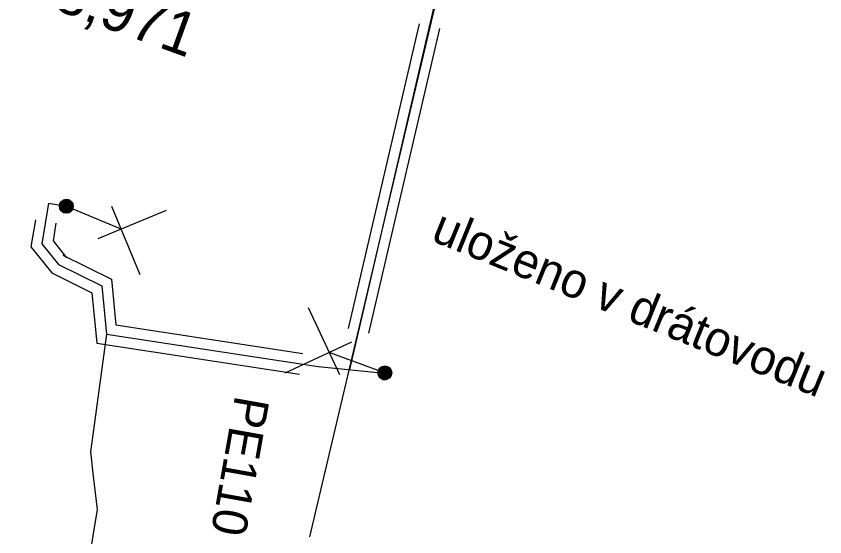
# Model space of a CAD drawing. Extents: x -731967 to -723173, y -945358 to -941505.
# Drawn here: x -725800 to -725776.75, y -942623.44 to -942608.48 of the extents above; entities that cross this region are included whole.
import ezdxf

# ---------------------------------------------------------------- set-up
doc = ezdxf.new("R2010")
doc.units = 0
for name, color, linetype in [('Vrstva 2', 7, 'Continuous'), ('Vrstva 28', 7, 'Continuous'), ('Vrstva 35', 7, 'Continuous')]:
    doc.layers.add(name, color=color, linetype=linetype)

msp = doc.modelspace()

# ---------------------------------------------------------------- linework, layer by layer
at = {"layer": 'Vrstva 2'}
for p, q in [((-725798.375, -942614.017), (-725796.99, -942614.592)), ((-725798.375, -942614.017), (-725796.99, -942614.592)), ((-725797.643, -942614.861), (-725795.683, -942614.051)), ((-725797.643, -942614.861), (-725795.683, -942614.051)), ((-725797.26, -942613.939), (-725796.45, -942615.9)), ((-725797.26, -942613.939), (-725796.45, -942615.9)), ((-725799.451, -942614.327), (-725799.577, -942615.102)), ((-725799.451, -942614.327), (-725799.577, -942615.102)), ((-725798.858, -942614.423), (-725798.942, -942614.937)), ((-725798.858, -942614.423), (-725798.942, -942614.937)), ((-725798.942, -942614.937), (-725798.555, -942615.423)), ((-725798.942, -942614.937), (-725798.555, -942615.423)), ((-725799.577, -942615.102), (-725798.981, -942615.85)), ((-725799.577, -942615.102), (-725798.981, -942615.85)), ((-725790.7, -942618.781), (-725791.595, -942616.857)), ((-725790.7, -942618.781), (-725791.595, -942616.857)), ((-725790.358, -942617.843), (-725792.282, -942618.738)), ((-725790.358, -942617.843), (-725792.282, -942618.738)), ((-725789.59, -942618.655), (-725790.999, -942618.141)), ((-725789.59, -942618.655), (-725790.999, -942618.141))]:
    msp.add_line(p, q, dxfattribs=at)
for points in [[(-725788.418, -942608.698), (-725790.454, -942617.453)], [(-725788.418, -942608.698), (-725790.454, -942617.453)], [(-725787.833, -942608.834), (-725789.87, -942617.589)], [(-725787.833, -942608.834), (-725789.87, -942617.589)], [(-725798.483, -942613.755), (-725798.59, -942613.746), (-725798.696, -942613.803), (-725798.747, -942613.906), (-725798.738, -942614.005), (-725798.671, -942614.093), (-725798.561, -942614.13), (-725798.462, -942614.104), (-725798.395, -942614.032), (-725798.373, -942613.921), (-725798.418, -942613.823), (-725798.496, -942613.772), (-725798.599, -942613.768), (-725798.691, -942613.827), (-725798.729, -942613.915), (-725798.718, -942614.007), (-725798.649, -942614.086), (-725798.551, -942614.111), (-725798.469, -942614.085), (-725798.406, -942614.012), (-725798.395, -942613.911), (-725798.437, -942613.831), (-725798.51, -942613.788), (-725798.606, -942613.791), (-725798.682, -942613.848), (-725798.711, -942613.922), (-725798.694, -942614.01), (-725798.627, -942614.076), (-725798.547, -942614.091), (-725798.472, -942614.063), (-725798.419, -942613.992), (-725798.416, -942613.907), (-725798.454, -942613.842), (-725798.525, -942613.804), (-725798.611, -942613.813), (-725798.67, -942613.863), (-725798.692, -942613.931), (-725798.671, -942614.01), (-725798.611, -942614.062), (-725798.545, -942614.071), (-725798.477, -942614.042), (-725798.434, -942613.976), (-725798.438, -942613.906), (-725798.472, -942613.853), (-725798.539, -942613.822), (-725798.61, -942613.835), (-725798.655, -942613.877), (-725798.673, -942613.941), (-725798.649, -942614.007), (-725798.598, -942614.045), (-725798.541, -942614.052), (-725798.482, -942614.021), (-725798.452, -942613.964), (-725798.456, -942613.909), (-725798.491, -942613.862), (-725798.55, -942613.84), (-725798.605, -942613.854), (-725798.641, -942613.891), (-725798.652, -942613.948), (-725798.63, -942614.001), (-725798.589, -942614.029), (-725798.538, -942614.03), (-725798.49, -942614.001), (-725798.471, -942613.957), (-725798.477, -942613.912), (-725798.508, -942613.873), (-725798.557, -942613.86), (-725798.597, -942613.873), (-725798.626, -942613.906), (-725798.633, -942613.953), (-725798.613, -942613.992), (-725798.58, -942614.01), (-725798.537, -942614.01), (-725798.503, -942613.984), (-725798.49, -942613.952), (-725798.496, -942613.914), (-725798.525, -942613.886), (-725798.559, -942613.88), (-725798.589, -942613.891), (-725798.61, -942613.919), (-725798.612, -942613.955), (-725798.596, -942613.979), (-725798.57, -942613.992), (-725798.539, -942613.99), (-725798.517, -942613.971), (-725798.508, -942613.946), (-725798.517, -942613.919), (-725798.538, -942613.902), (-725798.56, -942613.899), (-725798.58, -942613.908), (-725798.593, -942613.929), (-725798.593, -942613.952), (-725798.582, -942613.968), (-725798.563, -942613.974), (-725798.544, -942613.971), (-725798.533, -942613.958), (-725798.528, -942613.942), (-725798.534, -942613.927), (-725798.547, -942613.919), (-725798.559, -942613.919), (-725798.57, -942613.925)], [(-725798.483, -942613.755), (-725798.59, -942613.746), (-725798.696, -942613.803), (-725798.747, -942613.906), (-725798.738, -942614.005), (-725798.671, -942614.093), (-725798.561, -942614.13), (-725798.462, -942614.104), (-725798.395, -942614.032), (-725798.373, -942613.921), (-725798.418, -942613.823), (-725798.496, -942613.772), (-725798.599, -942613.768), (-725798.691, -942613.827), (-725798.729, -942613.915), (-725798.718, -942614.007), (-725798.649, -942614.086), (-725798.551, -942614.111), (-725798.469, -942614.085), (-725798.406, -942614.012), (-725798.395, -942613.911), (-725798.437, -942613.831), (-725798.51, -942613.788), (-725798.606, -942613.791), (-725798.682, -942613.848), (-725798.711, -942613.922), (-725798.694, -942614.01), (-725798.627, -942614.076), (-725798.547, -942614.091), (-725798.472, -942614.063), (-725798.419, -942613.992), (-725798.416, -942613.907), (-725798.454, -942613.842), (-725798.525, -942613.804), (-725798.611, -942613.813), (-725798.67, -942613.863), (-725798.692, -942613.931), (-725798.671, -942614.01), (-725798.611, -942614.062), (-725798.545, -942614.071), (-725798.477, -942614.042), (-725798.434, -942613.976), (-725798.438, -942613.906), (-725798.472, -942613.853), (-725798.539, -942613.822), (-725798.61, -942613.835), (-725798.655, -942613.877), (-725798.673, -942613.941), (-725798.649, -942614.007), (-725798.598, -942614.045), (-725798.541, -942614.052), (-725798.482, -942614.021), (-725798.452, -942613.964), (-725798.456, -942613.909), (-725798.491, -942613.862), (-725798.55, -942613.84), (-725798.605, -942613.854), (-725798.641, -942613.891), (-725798.652, -942613.948), (-725798.63, -942614.001), (-725798.589, -942614.029), (-725798.538, -942614.03), (-725798.49, -942614.001), (-725798.471, -942613.957), (-725798.477, -942613.912), (-725798.508, -942613.873), (-725798.557, -942613.86), (-725798.597, -942613.873), (-725798.626, -942613.906), (-725798.633, -942613.953), (-725798.613, -942613.992), (-725798.58, -942614.01), (-725798.537, -942614.01), (-725798.503, -942613.984), (-725798.49, -942613.952), (-725798.496, -942613.914), (-725798.525, -942613.886), (-725798.559, -942613.88), (-725798.589, -942613.891), (-725798.61, -942613.919), (-725798.612, -942613.955), (-725798.596, -942613.979), (-725798.57, -942613.992), (-725798.539, -942613.99), (-725798.517, -942613.971), (-725798.508, -942613.946), (-725798.517, -942613.919), (-725798.538, -942613.902), (-725798.56, -942613.899), (-725798.58, -942613.908), (-725798.593, -942613.929), (-725798.593, -942613.952), (-725798.582, -942613.968), (-725798.563, -942613.974), (-725798.544, -942613.971), (-725798.533, -942613.958), (-725798.528, -942613.942), (-725798.534, -942613.927), (-725798.547, -942613.919), (-725798.559, -942613.919), (-725798.57, -942613.925)], [(-725798.57, -942613.925), (-725798.575, -942613.936), (-725798.573, -942613.946), (-725798.567, -942613.953), (-725798.558, -942613.956), (-725798.55, -942613.953), (-725798.548, -942613.947), (-725798.547, -942613.941), (-725798.55, -942613.938), (-725798.554, -942613.937)], [(-725798.57, -942613.925), (-725798.575, -942613.936), (-725798.573, -942613.946), (-725798.567, -942613.953), (-725798.558, -942613.956), (-725798.55, -942613.953), (-725798.548, -942613.947), (-725798.547, -942613.941), (-725798.55, -942613.938), (-725798.554, -942613.937)], [(-725798.657, -942615.341), (-725797.257, -942616.035), (-725797.133, -942617.349), (-725791.765, -942618.168)], [(-725798.657, -942615.341), (-725797.257, -942616.035), (-725797.133, -942617.349), (-725791.765, -942618.168)], [(-725798.981, -942615.85), (-725797.823, -942616.425), (-725797.687, -942617.871), (-725791.856, -942618.762)], [(-725798.981, -942615.85), (-725797.823, -942616.425), (-725797.687, -942617.871), (-725791.856, -942618.762)], [(-725789.471, -942618.912), (-725789.364, -942618.917), (-725789.26, -942618.855), (-725789.214, -942618.75), (-725789.227, -942618.652), (-725789.298, -942618.566), (-725789.409, -942618.534), (-725789.507, -942618.564), (-725789.571, -942618.639), (-725789.588, -942618.751), (-725789.538, -942618.847), (-725789.459, -942618.895), (-725789.356, -942618.894), (-725789.266, -942618.831), (-725789.232, -942618.742), (-725789.247, -942618.651), (-725789.32, -942618.574), (-725789.419, -942618.554), (-725789.5, -942618.583), (-725789.559, -942618.659), (-725789.565, -942618.76), (-725789.52, -942618.838), (-725789.446, -942618.878), (-725789.349, -942618.871), (-725789.276, -942618.81), (-725789.251, -942618.736), (-725789.271, -942618.648), (-725789.341, -942618.586), (-725789.422, -942618.574), (-725789.495, -942618.605), (-725789.545, -942618.678), (-725789.544, -942618.764), (-725789.503, -942618.826), (-725789.431, -942618.861), (-725789.345, -942618.849), (-725789.289, -942618.796), (-725789.27, -942618.727), (-725789.294, -942618.65), (-725789.357, -942618.6), (-725789.423, -942618.594), (-725789.49, -942618.626), (-725789.529, -942618.693), (-725789.523, -942618.763), (-725789.486, -942618.815), (-725789.418, -942618.843), (-725789.348, -942618.827), (-725789.304, -942618.783), (-725789.289, -942618.718), (-725789.316, -942618.653), (-725789.368, -942618.617), (-725789.425, -942618.613), (-725789.483, -942618.646), (-725789.511, -942618.704), (-725789.504, -942618.759), (-725789.468, -942618.805), (-725789.408, -942618.824), (-725789.354, -942618.808), (-725789.319, -942618.769), (-725789.31, -942618.712), (-725789.335, -942618.66), (-725789.377, -942618.634), (-725789.428, -942618.635), (-725789.474, -942618.666), (-725789.492, -942618.711), (-725789.484, -942618.756), (-725789.451, -942618.793), (-725789.401, -942618.804), (-725789.362, -942618.79), (-725789.335, -942618.755), (-725789.33, -942618.708), (-725789.351, -942618.67), (-725789.385, -942618.654), (-725789.428, -942618.655), (-725789.461, -942618.682), (-725789.472, -942618.715), (-725789.464, -942618.752), (-725789.435, -942618.779), (-725789.401, -942618.784), (-725789.37, -942618.772), (-725789.351, -942618.743), (-725789.351, -942618.706), (-725789.368, -942618.683), (-725789.394, -942618.671), (-725789.426, -942618.675), (-725789.447, -942618.695), (-725789.454, -942618.72), (-725789.444, -942618.747), (-725789.423, -942618.763), (-725789.4, -942618.765), (-725789.38, -942618.755), (-725789.368, -942618.733), (-725789.369, -942618.71), (-725789.381, -942618.695), (-725789.4, -942618.69), (-725789.42, -942618.694), (-725789.43, -942618.707), (-725789.434, -942618.723), (-725789.427, -942618.738), (-725789.414, -942618.745), (-725789.402, -942618.745), (-725789.391, -942618.739)], [(-725789.471, -942618.912), (-725789.364, -942618.917), (-725789.26, -942618.855), (-725789.214, -942618.75), (-725789.227, -942618.652), (-725789.298, -942618.566), (-725789.409, -942618.534), (-725789.507, -942618.564), (-725789.571, -942618.639), (-725789.588, -942618.751), (-725789.538, -942618.847), (-725789.459, -942618.895), (-725789.356, -942618.894), (-725789.266, -942618.831), (-725789.232, -942618.742), (-725789.247, -942618.651), (-725789.32, -942618.574), (-725789.419, -942618.554), (-725789.5, -942618.583), (-725789.559, -942618.659), (-725789.565, -942618.76), (-725789.52, -942618.838), (-725789.446, -942618.878), (-725789.349, -942618.871), (-725789.276, -942618.81), (-725789.251, -942618.736), (-725789.271, -942618.648), (-725789.341, -942618.586), (-725789.422, -942618.574), (-725789.495, -942618.605), (-725789.545, -942618.678), (-725789.544, -942618.764), (-725789.503, -942618.826), (-725789.431, -942618.861), (-725789.345, -942618.849), (-725789.289, -942618.796), (-725789.27, -942618.727), (-725789.294, -942618.65), (-725789.357, -942618.6), (-725789.423, -942618.594), (-725789.49, -942618.626), (-725789.529, -942618.693), (-725789.523, -942618.763), (-725789.486, -942618.815), (-725789.418, -942618.843), (-725789.348, -942618.827), (-725789.304, -942618.783), (-725789.289, -942618.718), (-725789.316, -942618.653), (-725789.368, -942618.617), (-725789.425, -942618.613), (-725789.483, -942618.646), (-725789.511, -942618.704), (-725789.504, -942618.759), (-725789.468, -942618.805), (-725789.408, -942618.824), (-725789.354, -942618.808), (-725789.319, -942618.769), (-725789.31, -942618.712), (-725789.335, -942618.66), (-725789.377, -942618.634), (-725789.428, -942618.635), (-725789.474, -942618.666), (-725789.492, -942618.711), (-725789.484, -942618.756), (-725789.451, -942618.793), (-725789.401, -942618.804), (-725789.362, -942618.79), (-725789.335, -942618.755), (-725789.33, -942618.708), (-725789.351, -942618.67), (-725789.385, -942618.654), (-725789.428, -942618.655), (-725789.461, -942618.682), (-725789.472, -942618.715), (-725789.464, -942618.752), (-725789.435, -942618.779), (-725789.401, -942618.784), (-725789.37, -942618.772), (-725789.351, -942618.743), (-725789.351, -942618.706), (-725789.368, -942618.683), (-725789.394, -942618.671), (-725789.426, -942618.675), (-725789.447, -942618.695), (-725789.454, -942618.72), (-725789.444, -942618.747), (-725789.423, -942618.763), (-725789.4, -942618.765), (-725789.38, -942618.755), (-725789.368, -942618.733), (-725789.369, -942618.71), (-725789.381, -942618.695), (-725789.4, -942618.69), (-725789.42, -942618.694), (-725789.43, -942618.707), (-725789.434, -942618.723), (-725789.427, -942618.738), (-725789.414, -942618.745), (-725789.402, -942618.745), (-725789.391, -942618.739)], [(-725789.391, -942618.739), (-725789.387, -942618.727), (-725789.389, -942618.717), (-725789.396, -942618.71), (-725789.405, -942618.708), (-725789.412, -942618.712), (-725789.414, -942618.717), (-725789.415, -942618.724), (-725789.412, -942618.727), (-725789.407, -942618.727)], [(-725789.391, -942618.739), (-725789.387, -942618.727), (-725789.389, -942618.717), (-725789.396, -942618.71), (-725789.405, -942618.708), (-725789.412, -942618.712), (-725789.414, -942618.717), (-725789.415, -942618.724), (-725789.412, -942618.727), (-725789.407, -942618.727)]]:
    msp.add_lwpolyline(points, dxfattribs=at)
for centre in [(-725798.56, -942613.94), (-725798.56, -942613.94), (-725789.402, -942618.724), (-725789.402, -942618.724)]:
    msp.add_circle(centre, 0.2, dxfattribs=at)
at = {"layer": 'Vrstva 28'}
for p, q in [((-725799.07, -942613.85), (-725799.26, -942615.02)), ((-725799.07, -942613.85), (-725799.26, -942615.02)), ((-725799.26, -942615.02), (-725798.79, -942615.61)), ((-725799.26, -942615.02), (-725798.79, -942615.61))]:
    msp.add_line(p, q, dxfattribs=at)
for points in [[(-725787.74, -942607.35), (-725787.85, -942607.58), (-725790.42, -942618.63)], [(-725787.74, -942607.35), (-725787.85, -942607.58), (-725790.42, -942618.63)], [(-725799.07, -942613.85), (-725798.56, -942613.94)], [(-725799.07, -942613.85), (-725798.56, -942613.94)], [(-725798.79, -942615.61), (-725797.54, -942616.23), (-725797.41, -942617.61), (-725791.32, -942618.54), (-725789.41, -942618.73)], [(-725798.79, -942615.61), (-725797.54, -942616.23), (-725797.41, -942617.61), (-725791.32, -942618.54), (-725789.41, -942618.73)], [(-725797.41, -942617.61), (-725797.87, -942620.99), (-725797.79, -942621.69), (-725797.67, -942622.65), (-725798.64, -942628.53), (-725800.57, -942636.27), (-725802.27, -942643.96), (-725804.04, -942650.75), (-725805.98, -942658.04), (-725807.32, -942662.1), (-725808.42, -942665.74), (-725809.26, -942668.88), (-725811.57, -942674.84), (-725813.06, -942680.22), (-725814.79, -942685.21), (-725815.96, -942687.34), (-725818.65, -942689.62), (-725819.3, -942690), (-725817.32, -942691.31), (-725813.15, -942693.04), (-725812.37, -942693.27), (-725812.04, -942692.89)], [(-725797.41, -942617.61), (-725797.87, -942620.99), (-725797.79, -942621.69), (-725797.67, -942622.65), (-725798.64, -942628.53), (-725800.57, -942636.27), (-725802.27, -942643.96), (-725804.04, -942650.75), (-725805.98, -942658.04), (-725807.32, -942662.1), (-725808.42, -942665.74), (-725809.26, -942668.88), (-725811.57, -942674.84), (-725813.06, -942680.22), (-725814.79, -942685.21), (-725815.96, -942687.34), (-725818.65, -942689.62), (-725819.3, -942690), (-725817.32, -942691.31), (-725813.15, -942693.04), (-725812.37, -942693.27), (-725812.04, -942692.89)]]:
    msp.add_lwpolyline(points, dxfattribs=at)
at = {"layer": 'Vrstva 35'}
msp.add_line((-725786.975, -942603.978), (-725791.571, -942623.436), dxfattribs=at)

# ---------------------------------------------------------------- texts
at = {"layer": 'Vrstva 2'}
for s, rotation, p in [('uloženo v drátovodu', 337.9041, (-725788.114, -942614.911)), ('uloženo v drátovodu', 337.9041, (-725788.114, -942614.911)), ('PE110', 259.9157, (-725793.702, -942619.344)), ('PE110', 259.9157, (-725793.702, -942619.344))]:
    msp.add_text(s, height=1, rotation=rotation, dxfattribs=at).set_placement(p)
at = {"layer": 'Vrstva 28'}
msp.add_text('P3540, km 8,971', height=1.24131, rotation=340.0711, dxfattribs=at).set_placement((-725806.874, -942605.396))

doc.saveas('drawing.dxf')
